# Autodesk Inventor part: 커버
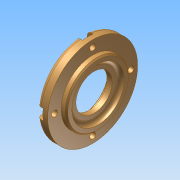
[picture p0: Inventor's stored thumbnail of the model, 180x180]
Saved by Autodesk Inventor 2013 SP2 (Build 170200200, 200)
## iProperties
Created: 2025-08
Part Number: 커버
Material: Generic
Document SubType Name: Modeling
Designer: i
Density: 1 g/cm^3
Author: i
변환 표준: STEP AP214IS
전처리기: Build: 200, Release: 2013 SP2 Update 6 - Date: Thu 07/17/2014
전송 단위: 밀리미터
불확실성: 0.01
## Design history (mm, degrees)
node "커버1"
node "솔리드1"
node "기준1"
